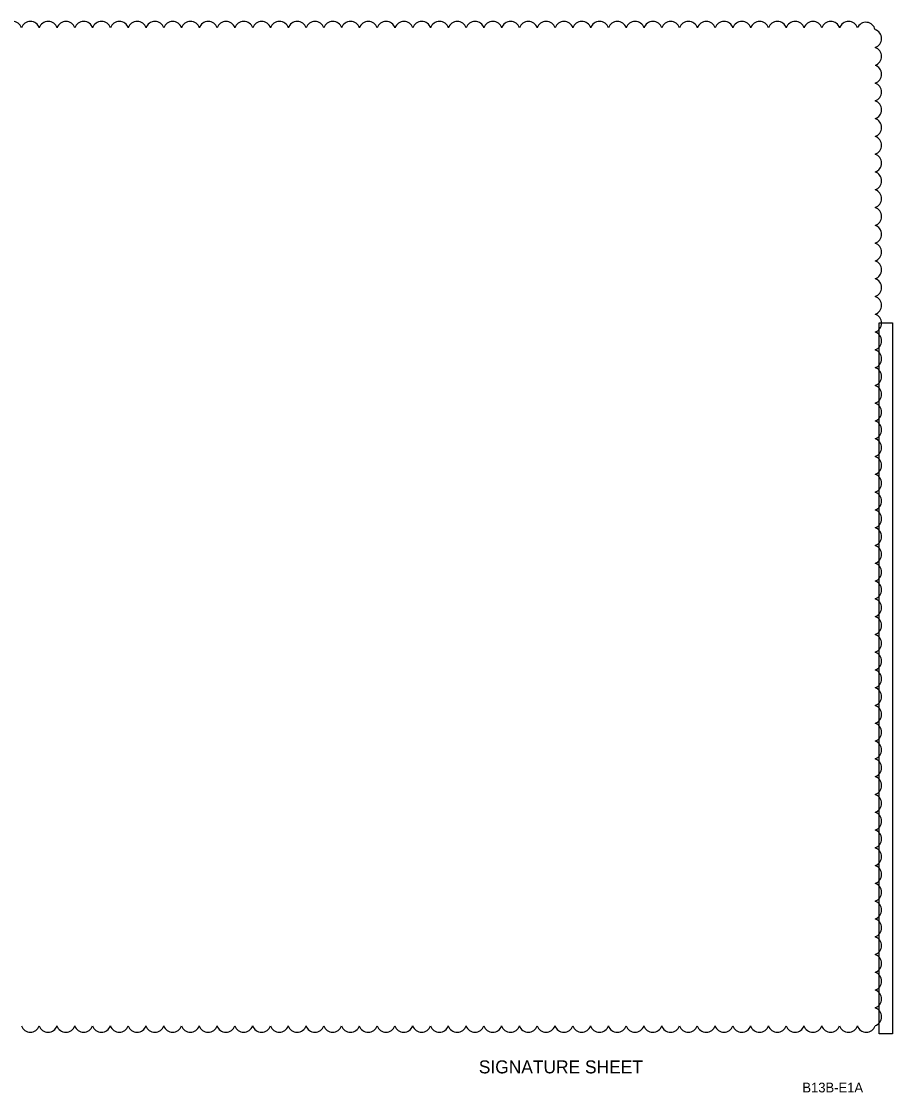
# Model space of a CAD drawing. Extents: x -811.3 to -795.2, y -2199.5 to -2188.9.
# Drawn here: x -803.6 to -795.22, y -2199.24 to -2188.94 of the extents above; entities that cross this region are included whole.
import ezdxf

# ---------------------------------------------------------------- set-up
doc = ezdxf.new("R2010")
doc.units = 0
for name, color, linetype in [('AdhocPoint_dp', 7, 'Continuous'), ('ScratchEle_dp', 7, 'Continuous'), ('SheetBorder_dp', 7, 'Continuous'), ('TextMisc', 7, 'Continuous')]:
    doc.layers.add(name, color=color, linetype=linetype)

msp = doc.modelspace()

# ---------------------------------------------------------------- linework, layer by layer
at = {"layer": 'ScratchEle_dp'}
for centre, radius, start, end in [((-803.684, -2189.028), 0.0897, 17.5, 162.5), ((-803.513, -2189.028), 0.0897, 17.5, 162.5), ((-803.342, -2189.028), 0.0897, 17.5, 162.5), ((-803.171, -2189.028), 0.0897, 17.5, 162.5), ((-803, -2189.028), 0.0897, 17.5, 162.5), ((-802.829, -2189.028), 0.0897, 17.5, 162.5), ((-802.657, -2189.028), 0.0897, 17.5, 162.5), ((-802.486, -2189.028), 0.0897, 17.5, 162.5), ((-802.315, -2189.028), 0.0897, 17.5, 162.5), ((-802.144, -2189.028), 0.0897, 17.5, 162.5), ((-801.973, -2189.028), 0.0897, 17.5, 162.5), ((-801.802, -2189.028), 0.0897, 17.5, 162.5), ((-801.631, -2189.028), 0.0897, 17.5, 162.5), ((-801.46, -2189.028), 0.0897, 17.5, 162.5), ((-801.288, -2189.028), 0.0897, 17.5, 162.5), ((-801.117, -2189.028), 0.0897, 17.5, 162.5), ((-800.946, -2189.028), 0.0897, 17.5, 162.5), ((-800.775, -2189.028), 0.0897, 17.5, 162.5), ((-800.604, -2189.028), 0.0897, 17.5, 162.5), ((-800.433, -2189.028), 0.0897, 17.5, 162.5), ((-800.262, -2189.028), 0.0897, 17.5, 162.5), ((-800.091, -2189.028), 0.0897, 17.5, 162.5), ((-799.919, -2189.028), 0.0897, 17.5, 162.5), ((-799.748, -2189.028), 0.0897, 17.5, 162.5), ((-799.577, -2189.028), 0.0897, 17.5, 162.5), ((-799.406, -2189.028), 0.0897, 17.5, 162.5), ((-799.235, -2189.028), 0.0897, 17.5, 162.5), ((-799.064, -2189.028), 0.0897, 17.5, 162.5), ((-798.893, -2189.028), 0.0897, 17.5, 162.5), ((-798.722, -2189.028), 0.0897, 17.5, 162.5), ((-798.551, -2189.028), 0.0897, 17.5, 162.5), ((-798.379, -2189.028), 0.0897, 17.5, 162.5), ((-798.208, -2189.028), 0.0897, 17.5, 162.5), ((-798.037, -2189.028), 0.0897, 17.5, 162.5), ((-797.866, -2189.028), 0.0897, 17.5, 162.5), ((-797.695, -2189.028), 0.0897, 17.5, 162.5), ((-797.524, -2189.028), 0.0897, 17.5, 162.5), ((-797.353, -2189.028), 0.0897, 17.5, 162.5), ((-797.182, -2189.028), 0.0897, 17.5, 162.5), ((-797.01, -2189.028), 0.0897, 17.5, 162.5), ((-796.839, -2189.028), 0.0897, 17.5, 162.5), ((-796.668, -2189.028), 0.0897, 17.5, 162.5), ((-796.497, -2189.028), 0.0897, 17.5, 162.5), ((-796.326, -2189.028), 0.0897, 17.5, 162.5), ((-796.155, -2189.028), 0.0897, 17.5, 162.5), ((-795.984, -2189.028), 0.0897, 17.5, 162.5), ((-795.813, -2189.028), 0.0897, 17.5, 162.5), ((-795.641, -2189.028), 0.0897, 17.5, 162.5), ((-795.474, -2189.036), 0.0896, 11.7454, 156.7454), ((-795.413, -2189.103), 0.0897, 287.5, 72.5), ((-795.413, -2189.274), 0.0897, 287.5, 72.5), ((-795.413, -2189.446), 0.0897, 287.5, 72.5), ((-795.413, -2189.617), 0.0897, 287.5, 72.5), ((-795.413, -2189.788), 0.0897, 287.5, 72.5), ((-795.413, -2189.959), 0.0897, 287.5, 72.5), ((-795.413, -2190.13), 0.0897, 287.5, 72.5), ((-795.413, -2190.301), 0.0897, 287.5, 72.5), ((-795.413, -2190.472), 0.0897, 287.5, 72.5), ((-795.413, -2190.643), 0.0897, 287.5, 72.5), ((-795.413, -2190.815), 0.0897, 287.5, 72.5), ((-795.413, -2190.986), 0.0897, 287.5, 72.5), ((-795.413, -2191.157), 0.0897, 287.5, 72.5), ((-795.413, -2191.328), 0.0897, 287.5, 72.5), ((-795.413, -2191.499), 0.0897, 287.5, 72.5), ((-795.413, -2191.67), 0.0897, 287.5, 72.5), ((-795.413, -2191.841), 0.0897, 287.5, 72.5), ((-795.413, -2192.012), 0.0897, 287.5, 72.5), ((-795.413, -2192.184), 0.0897, 287.5, 72.5), ((-795.413, -2192.355), 0.0897, 287.5, 72.5), ((-795.413, -2192.526), 0.0897, 287.5, 72.5), ((-795.413, -2192.697), 0.0897, 287.5, 72.5), ((-795.413, -2192.868), 0.0897, 287.5, 72.5), ((-795.413, -2193.039), 0.0897, 287.5, 72.5), ((-795.413, -2193.21), 0.0897, 287.5, 72.5), ((-795.413, -2193.381), 0.0897, 287.5, 72.5), ((-795.413, -2193.553), 0.0897, 287.5, 72.5), ((-795.413, -2193.724), 0.0897, 287.5, 72.5), ((-795.413, -2193.895), 0.0897, 287.5, 72.5), ((-795.413, -2194.066), 0.0897, 287.5, 72.5), ((-795.413, -2194.237), 0.0897, 287.5, 72.5), ((-795.413, -2194.408), 0.0897, 287.5, 72.5), ((-795.413, -2194.579), 0.0897, 287.5, 72.5), ((-795.413, -2194.75), 0.0897, 287.5, 72.5), ((-795.413, -2194.922), 0.0897, 287.5, 72.5), ((-795.413, -2195.093), 0.0897, 287.5, 72.5), ((-795.413, -2195.264), 0.0897, 287.5, 72.5), ((-795.413, -2195.435), 0.0897, 287.5, 72.5), ((-795.413, -2195.606), 0.0897, 287.5, 72.5), ((-795.413, -2195.777), 0.0897, 287.5, 72.5), ((-795.413, -2195.948), 0.0897, 287.5, 72.5), ((-795.413, -2196.119), 0.0897, 287.5, 72.5), ((-795.413, -2196.29), 0.0897, 287.5, 72.5), ((-795.413, -2196.462), 0.0897, 287.5, 72.5), ((-795.413, -2196.633), 0.0897, 287.5, 72.5), ((-795.413, -2196.804), 0.0897, 287.5, 72.5), ((-795.413, -2196.975), 0.0897, 287.5, 72.5), ((-795.413, -2197.146), 0.0897, 287.5, 72.5), ((-795.413, -2197.317), 0.0897, 287.5, 72.5), ((-795.413, -2197.488), 0.0897, 287.5, 72.5), ((-795.413, -2197.659), 0.0897, 287.5, 72.5), ((-795.413, -2197.831), 0.0897, 287.5, 72.5), ((-795.413, -2198.002), 0.0897, 287.5, 72.5), ((-795.413, -2198.173), 0.0897, 287.5, 72.5), ((-795.413, -2198.344), 0.0897, 287.5, 72.5), ((-795.413, -2198.515), 0.0897, 287.5, 72.5), ((-803.514, -2198.574), 0.0897, 197.5, 342.5), ((-803.343, -2198.574), 0.0897, 197.5, 342.5), ((-803.172, -2198.574), 0.0897, 197.5, 342.5), ((-803.001, -2198.574), 0.0897, 197.5, 342.5), ((-802.83, -2198.574), 0.0897, 197.5, 342.5), ((-802.658, -2198.574), 0.0897, 197.5, 342.5), ((-802.487, -2198.574), 0.0897, 197.5, 342.5), ((-802.316, -2198.574), 0.0897, 197.5, 342.5), ((-802.145, -2198.574), 0.0897, 197.5, 342.5), ((-801.974, -2198.574), 0.0897, 197.5, 342.5), ((-801.803, -2198.574), 0.0897, 197.5, 342.5), ((-801.632, -2198.574), 0.0897, 197.5, 342.5), ((-801.461, -2198.574), 0.0897, 197.5, 342.5), ((-801.289, -2198.574), 0.0897, 197.5, 342.5), ((-801.118, -2198.574), 0.0897, 197.5, 342.5), ((-800.947, -2198.574), 0.0897, 197.5, 342.5), ((-800.776, -2198.574), 0.0897, 197.5, 342.5), ((-800.605, -2198.574), 0.0897, 197.5, 342.5), ((-800.434, -2198.574), 0.0897, 197.5, 342.5), ((-800.263, -2198.574), 0.0897, 197.5, 342.5), ((-800.092, -2198.574), 0.0897, 197.5, 342.5), ((-799.921, -2198.574), 0.0897, 197.5, 342.5), ((-799.749, -2198.574), 0.0897, 197.5, 342.5), ((-799.578, -2198.574), 0.0897, 197.5, 342.5), ((-799.407, -2198.574), 0.0897, 197.5, 342.5), ((-799.236, -2198.574), 0.0897, 197.5, 342.5), ((-799.065, -2198.574), 0.0897, 197.5, 342.5), ((-798.894, -2198.574), 0.0897, 197.5, 342.5), ((-798.723, -2198.574), 0.0897, 197.5, 342.5), ((-798.552, -2198.574), 0.0897, 197.5, 342.5), ((-798.38, -2198.574), 0.0897, 197.5, 342.5), ((-798.209, -2198.574), 0.0897, 197.5, 342.5), ((-798.038, -2198.574), 0.0897, 197.5, 342.5), ((-797.867, -2198.574), 0.0897, 197.5, 342.5), ((-797.696, -2198.574), 0.0897, 197.5, 342.5), ((-797.525, -2198.574), 0.0897, 197.5, 342.5), ((-797.354, -2198.574), 0.0897, 197.5, 342.5), ((-797.183, -2198.574), 0.0897, 197.5, 342.5), ((-797.011, -2198.574), 0.0897, 197.5, 342.5), ((-796.84, -2198.574), 0.0897, 197.5, 342.5), ((-796.669, -2198.574), 0.0897, 197.5, 342.5), ((-796.498, -2198.574), 0.0897, 197.5, 342.5), ((-796.327, -2198.574), 0.0897, 197.5, 342.5), ((-796.156, -2198.574), 0.0897, 197.5, 342.5), ((-795.985, -2198.574), 0.0897, 197.5, 342.5), ((-795.814, -2198.574), 0.0897, 197.5, 342.5), ((-795.642, -2198.574), 0.0897, 197.5, 342.5), ((-795.471, -2198.574), 0.0897, 197.5, 342.5)]:
    msp.add_arc(centre, radius, start, end, dxfattribs=at)
at = {"layer": 'TextMisc'}
msp.add_lwpolyline([(-795.346, -2191.838), (-795.218, -2191.838), (-795.218, -2198.68), (-795.346, -2198.68)], close=True, dxfattribs=at)

# ---------------------------------------------------------------- texts
at = {"layer": 'AdhocPoint_dp'}
msp.add_text('B13B-E1A', height=0.0936, dxfattribs=at).set_placement((-796.086, -2199.243))
at = {"layer": 'SheetBorder_dp'}
msp.add_text('       SIGNATURE SHEET         ', height=0.125, dxfattribs=at).set_placement((-799.524, -2199.06))

doc.saveas('drawing.dxf')
